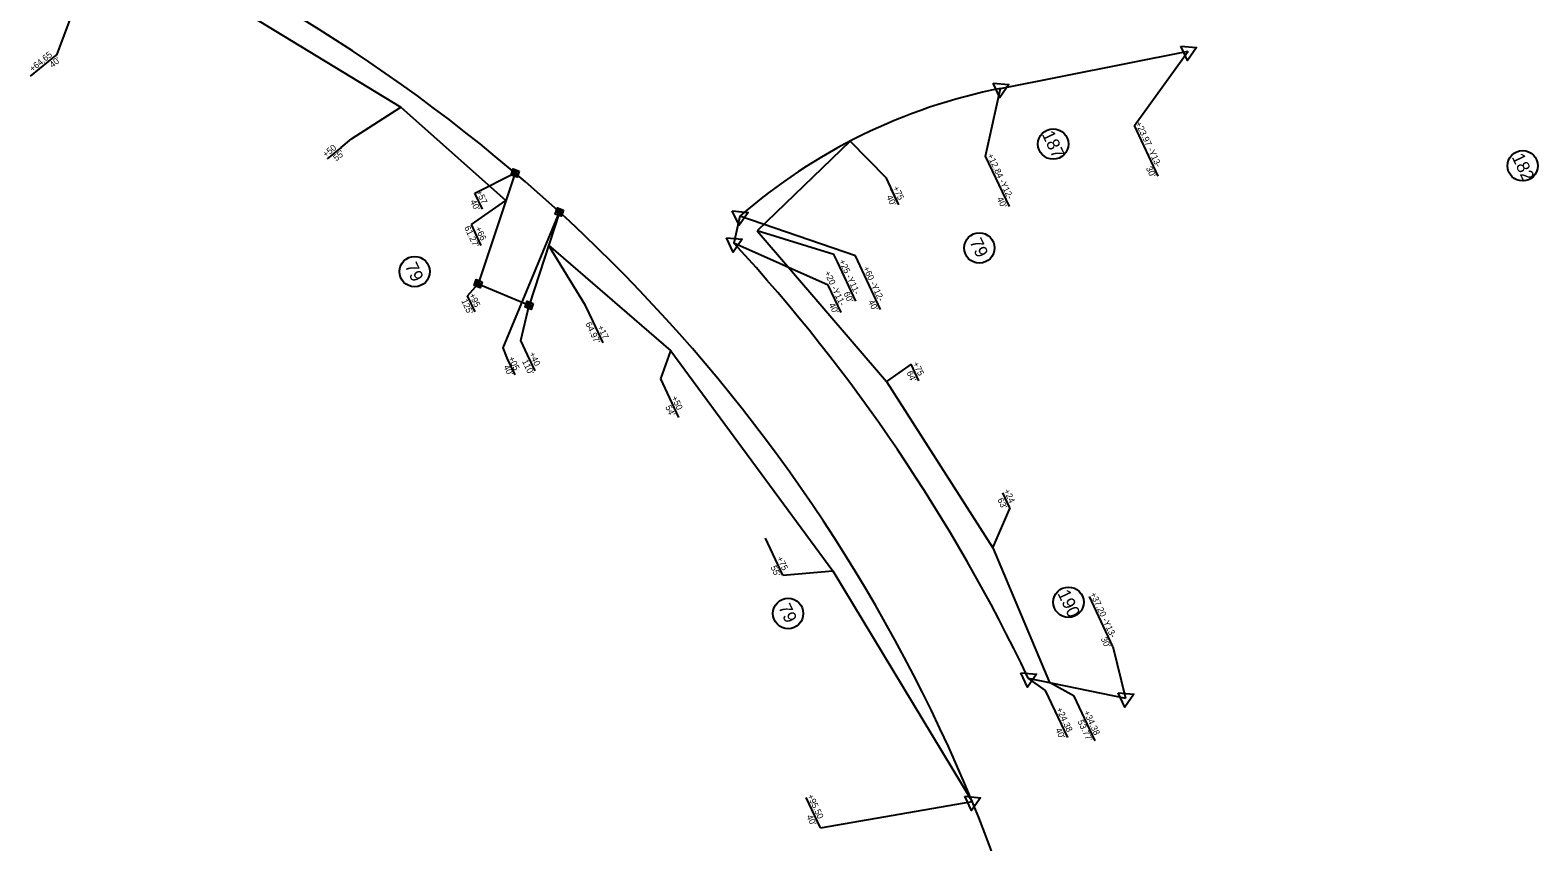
# Model space of a CAD drawing. Extents: x 2320946 to 2332748, y 597838 to 612698.
# Drawn here: x 2326579 to 2327769, y 601121 to 601762 of the extents above; entities that cross this region are included whole.
import ezdxf

# ---------------------------------------------------------------- set-up
doc = ezdxf.new("R2010")
doc.units = 0
for name, color, linetype in [('Prop Easement Construction', 7, 'Continuous'), ('Prop Easement Construction Station Offsets', 7, 'Continuous'), ('Prop Easement Permanent Drainage', 7, 'Continuous'), ('Prop Easement Permanent Drainage Station Offsets', 7, 'Continuous'), ('Prop Parcel Number CELL', 7, 'Continuous'), ('Prop ROW Marker CELL', 7, 'Continuous'), ('Prop ROW Permanent Easement CELL', 7, 'Continuous'), ('Prop ROW RW Lines', 7, 'Continuous'), ('Prop ROW Station Offsets', 7, 'Continuous')]:
    doc.layers.add(name, color=color, linetype=linetype)

msp = doc.modelspace()

# ---------------------------------------------------------------- linework, layer by layer
at = {"layer": 'Prop Easement Construction'}
for p, q in [((2327226, 601674.1), (2327152.6, 601603.3)), ((2327152.6, 601603.3), (2327254.9, 601484.4)), ((2326988, 601592), (2327084.5, 601508.5)), ((2327254.9, 601484.4), (2327338.8, 601352.9)), ((2327338.8, 601352.9), (2327383.6, 601246.5))]:
    msp.add_line(p, q, dxfattribs=at)
for points in [[(2326699.5, 601805.9), (2326871.2, 601700.9), (2326954.3, 601627.2)], [(2327084.5, 601508.5), (2327212.3, 601334.7), (2327322.5, 601152.5)]]:
    msp.add_lwpolyline(points, dxfattribs=at)
at = {"layer": 'Prop Easement Construction Station Offsets'}
for p, q in [((2326824.1, 601669.2), (2326813.1, 601660.3)), ((2327264.5, 601623.9), (2327258.5, 601636.6)), ((2326934.8, 601591.7), (2326927, 601608.2)), ((2327230.6, 601547.7), (2327216, 601578.7)), ((2327031, 601514.7), (2327022.8, 601532.2)), ((2327274.2, 601497.9), (2327254.9, 601484.4)), ((2327280.3, 601484.8), (2327274.2, 601497.9)), ((2327090.9, 601455.8), (2327076.5, 601486.3)), ((2327352.1, 601384.6), (2327346.6, 601396.2)), ((2327173, 601331.2), (2327159.2, 601360.4)), ((2327419.5, 601200.4), (2327402.9, 601235.8))]:
    msp.add_line(p, q, dxfattribs=at)
for points in [[(2326824.1, 601669.2), (2326832.3, 601676), (2326871.2, 601700.9)], [(2327264.5, 601623.9), (2327254.7, 601644.8), (2327226, 601674.1)], [(2326927, 601608.2), (2326954.3, 601627.2)], [(2327216, 601578.7), (2327213.2, 601584.7), (2327152.6, 601603.3)], [(2327022.8, 601532.2), (2327017, 601544.4), (2326988, 601592)], [(2327076.5, 601486.3), (2327084.5, 601508.5)], [(2327352.1, 601384.6), (2327338.6, 601352.8)], [(2327173, 601331.2), (2327212.3, 601334.7)], [(2327402.9, 601235.8), (2327383.6, 601246.5)]]:
    msp.add_lwpolyline(points, dxfattribs=at)
at = {"layer": 'Prop Easement Permanent Drainage'}
for p, q in [((2326961.6, 601649), (2326932.4, 601561.5)), ((2326996.5, 601618.1), (2326972.7, 601544.5)), ((2326932.4, 601561.5), (2326972.7, 601544.5))]:
    msp.add_line(p, q, dxfattribs=at)
at = {"layer": 'Prop Easement Permanent Drainage Station Offsets'}
for p, q in [((2326935.7, 601620.3), (2326929.7, 601633.1)), ((2326929.9, 601539.3), (2326924, 601551.9)), ((2326961.5, 601489.5), (2326955.5, 601502.2)), ((2326977.4, 601492.6), (2326971.4, 601505.4))]:
    msp.add_line(p, q, dxfattribs=at)
for points in [[(2326929.7, 601633.1), (2326961.6, 601649)], [(2326955.5, 601502.2), (2326952, 601511), (2326996.5, 601618.1)], [(2326924, 601551.9), (2326932.4, 601561.5)], [(2326971.4, 601505.4), (2326966.1, 601516.7), (2326972.7, 601544.5)]]:
    msp.add_lwpolyline(points, dxfattribs=at)
at = {"layer": 'Prop Parcel Number CELL'}
for p, q in [((2327386.4, 601671.9), (2327386.4, 601671.9)), ((2327757.1, 601654.7), (2327757.1, 601654.7)), ((2327328.1, 601589.8), (2327328.1, 601589.8)), ((2326882.2, 601571.1), (2326882.2, 601571.1)), ((2327398.5, 601309.9), (2327398.5, 601309.9)), ((2327177.1, 601301), (2327177.1, 601301))]:
    msp.add_line(p, q, dxfattribs=at)
for centre in [(2327386.4, 601671.9), (2327757.1, 601654.7), (2327328.1, 601589.8), (2326882.2, 601571.1), (2327398.5, 601309.9), (2327177.1, 601301)]:
    msp.add_circle(centre, 12, dxfattribs=at)
at = {"layer": 'Prop ROW Marker CELL'}
for p, q in [((2327493.1, 601745.2), (2327493.1, 601745.2)), ((2327344.9, 601715.8), (2327344.9, 601715.8)), ((2326961.6, 601649), (2326961.6, 601649)), ((2326996.5, 601618.1), (2326996.5, 601618.1)), ((2327139, 601614.8), (2327139, 601614.8)), ((2327134.3, 601593.6), (2327134.3, 601593.6)), ((2326932.4, 601561.5), (2326932.4, 601561.5)), ((2326972.7, 601544.5), (2326972.7, 601544.5)), ((2327366.7, 601249.9), (2327366.7, 601249.9)), ((2327443.5, 601234.1), (2327443.5, 601234.1)), ((2327322.5, 601152.5), (2327322.5, 601152.5))]:
    msp.add_line(p, q, dxfattribs=at)
for points in [[(2327487.2, 601749.3), (2327499.6, 601748.2), (2327492.5, 601738)], [(2327339, 601720), (2327351.4, 601718.9), (2327344.3, 601708.7)], [(2327133, 601619), (2327145.5, 601617.9), (2327138.4, 601607.7)], [(2327128.4, 601597.7), (2327140.9, 601596.6), (2327133.8, 601586.4)], [(2327360.8, 601254.1), (2327373.2, 601253), (2327366.1, 601242.8)], [(2327437.6, 601238.3), (2327450, 601237.2), (2327442.9, 601227)], [(2327316.6, 601156.6), (2327329.1, 601155.5), (2327322, 601145.3)]]:
    msp.add_lwpolyline(points, close=True, dxfattribs=at)
at = {"layer": 'Prop ROW Permanent Easement CELL'}
for points in [[(2326964.8, 601650.5), (2326963.1, 601645.7), (2326958.3, 601647.4), (2326960.1, 601652.2)], [(2326963.2, 601649.7), (2326962.4, 601647.3), (2326960, 601648.2), (2326960.8, 601650.6)], [(2326999.8, 601619.7), (2326998, 601614.9), (2326993.2, 601616.6), (2326995, 601621.4)], [(2326998.1, 601618.9), (2326997.3, 601616.5), (2326994.9, 601617.4), (2326995.7, 601619.7)], [(2326935.6, 601563.1), (2326933.9, 601558.3), (2326929.1, 601560), (2326930.9, 601564.8)], [(2326934, 601562.3), (2326933.2, 601559.9), (2326930.8, 601560.8), (2326931.6, 601563.2)], [(2326975.9, 601546), (2326974.2, 601541.2), (2326969.4, 601542.9), (2326971.1, 601547.7)], [(2326974.3, 601545.2), (2326973.4, 601542.8), (2326971, 601543.7), (2326971.9, 601546.1)]]:
    msp.add_lwpolyline(points, close=True, dxfattribs=at)
at = {"layer": 'Prop ROW RW Lines'}
for p, q in [((2327344.9, 601715.8), (2327493.1, 601745.2)), ((2327139, 601614.8), (2327134.3, 601593.6)), ((2327366.7, 601249.9), (2327443.5, 601234.1))]:
    msp.add_line(p, q, dxfattribs=at)
for centre, radius, start, end in [((2326112, 600651.8), 1310, 22.4692, 66.2198), ((2327431.3, 601279.3), 445, 101.1907, 131.0597), ((2326112, 600651.8), 1390, 25.4874, 42.65), ((2326527.8, 600823.8), 860, 353.8058, 22.4692)]:
    msp.add_arc(centre, radius, start, end, dxfattribs=at)
at = {"layer": 'Prop ROW Station Offsets'}
for p, q in [((2326600, 601742.9), (2326578.6, 601725.4)), ((2327450.6, 601686.5), (2327493.1, 601745.2)), ((2327469.4, 601646.6), (2327450.6, 601686.5)), ((2327351.8, 601622.4), (2327332.9, 601662.4)), ((2327230.2, 601583.6), (2327139, 601614.8)), ((2327250.1, 601541.2), (2327230.2, 601583.6)), ((2327219, 601538.7), (2327208.7, 601560.5)), ((2327433.6, 601274.9), (2327415.1, 601314.3)), ((2327397.9, 601203), (2327380.3, 601240.3)), ((2327202.7, 601131.6), (2327191.4, 601155.6)), ((2327202.7, 601131.6), (2327322.5, 601152.5))]:
    msp.add_line(p, q, dxfattribs=at)
for points in [[(2326600, 601742.9), (2326640.2, 601850.6)], [(2327332.9, 601662.4), (2327344.9, 601715.8)], [(2327208.7, 601560.5), (2327134.3, 601593.6)], [(2327433.6, 601274.9), (2327443.5, 601234.1)], [(2327380.3, 601240.3), (2327366.7, 601249.9)]]:
    msp.add_lwpolyline(points, dxfattribs=at)

# ---------------------------------------------------------------- texts
at = {"layer": 'Prop Easement Construction Station Offsets'}
for s, rotation, p in [('+50', 39.228, (2326812.1, 601661)), ("55'", 39.228, (2326820.4, 601658.1)), ("40'", 295.2142, (2327254.6, 601630.2)), ('+75', 295.2142, (2327259.6, 601637.4)), ("61.27'", 295.2142, (2326921.2, 601605.9)), ('+66', 295.2142, (2326929.8, 601605.3)), ('+25 -Y11-', 295.2142, (2327217.1, 601579.3)), ("60'", 295.2142, (2327220.7, 601553.9)), ("64.97'", 295.2142, (2327016.9, 601529.9)), ('+17', 295.2142, (2327026.4, 601527.4)), ('+75 ', 295.2158, (2327275.4, 601498.5)), ("64'", 295.2158, (2327270.5, 601491.3)), ("54'", 295.2158, (2327080, 601464.2)), ('+50 ', 295.2158, (2327084.8, 601471.5)), ("63'", 295.2158, (2327342.2, 601390.9)), ('+24 ', 295.2158, (2327347.2, 601398)), ('+75 ', 295.2158, (2327168, 601344.7)), ("55'", 295.2158, (2327163.1, 601337.5)), ("53.77'", 295.2158, (2327405.5, 601215.7)), ('+34.38 ', 295.2158, (2327410.3, 601223))]:
    msp.add_text(s, height=5, rotation=rotation, dxfattribs=at).set_placement(p)
at = {"layer": 'Prop Easement Permanent Drainage Station Offsets'}
for s, p in [('+57', (2326930.6, 601634.1)), ("40'", (2326925.9, 601626.6)), ("125'", (2326918.9, 601548)), ('+95', (2326925, 601552.7)), ('+05', (2326956, 601502.7)), ("110'", (2326966.9, 601500.3)), ('+40', (2326972.4, 601506.2)), ("40' ", (2326952.2, 601496.1))]:
    msp.add_text(s, height=5, rotation=295.2142, dxfattribs=at).set_placement(p)
at = {"layer": 'Prop Parcel Number CELL'}
for s, rotation, p in [('187', 295.2142, (2327377.3, 601679.6)), ('182', 295.2142, (2327748.3, 601661.7)), ('79', 295.2142, (2327320.2, 601594.7)), ('79', 295.2158, (2326874.3, 601575.6)), ('79', 295.2142, (2327169.2, 601306)), ('190', 295.2142, (2327389.6, 601317))]:
    msp.add_text(s, height=10, rotation=rotation, dxfattribs=at).set_placement(p)
at = {"layer": 'Prop ROW Station Offsets'}
for s, rotation, p in [('+64.65 ', 39.228, (2326580.5, 601728.6)), ("40'", 39.228, (2326596.3, 601731.8)), ('+23.97 -Y13-', 295.2158, (2327451.2, 601688.2)), ('+12.84 -Y12-', 295.2158, (2327334.1, 601663)), ("30'", 295.2158, (2327459.5, 601652.8)), ("40'", 295.2158, (2327341.9, 601628.7)), ('+20 -Y11-', 295.2158, (2327205.5, 601570.3)), ('+60 -Y12-', 295.2158, (2327236.1, 601573.9)), ("40'", 295.2158, (2327240.2, 601547.5)), ("40'", 295.2158, (2327209.1, 601545)), ('+37.20 -Y13- ', 295.2158, (2327415.4, 601316.5)), ("30'", 295.2158, (2327423.8, 601281.1)), ('+24.38 ', 295.2158, (2327388.7, 601225.5)), ("40'", 295.2158, (2327388, 601209.2)), ('+95.50 ', 295.2158, (2327192.1, 601156.9)), ("40'", 295.2158, (2327191.5, 601140.7))]:
    msp.add_text(s, height=5, rotation=rotation, dxfattribs=at).set_placement(p)

doc.saveas('drawing.dxf')
